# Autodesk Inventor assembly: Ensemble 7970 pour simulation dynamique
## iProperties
Created: 2011-10
Part Number: Ensemble 7970 pour simulation dynamique
Document SubType Name: Assembly
Designer: Laur
Author: Laur
